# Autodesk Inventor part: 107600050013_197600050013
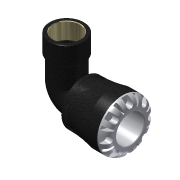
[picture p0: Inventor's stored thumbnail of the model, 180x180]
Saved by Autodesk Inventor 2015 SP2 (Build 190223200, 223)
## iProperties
Created: 2016-12
Part Number: 107600050013_197600050013
Material: PVC-Piping
Description: PLASSON 90° ELBOW WITH FEMALE INTEGRAL BRASS 50X1.1/4" SERIES 1
Document SubType Name: Modeling
Designer: KIM
Mass: 664.223 g
Surface Area: 733.008 cm^2
Volume: 474.445 cm^3
Density: 1.4 g/cm^3
Appearance: Black Cast
Author: KIM
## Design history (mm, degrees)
derived "1076.ipt"
feature "Solid1::1076.ipt"
tag "TaggingFeature1"
body "Solid1"
other parameters: "d1" = 33.18, "d3" = 62.5, "d4" = 85, "d8" = 74.8, "d13" = 9, "d14" = 9, "d15" = 0, "d17" = 360 deg, "d19" = 8 deg, "d20" = 1, "d21" = 1, "d22" = 8 deg, "d24" = 0, "d26" = 360 deg, "d33" = 8.5, "d51" = 0.85, "d54" = 17.5, "d55" = 11, "d57" = 17.64, "d58" = 0, "d74" = 0, "d78" = 79, "d82" = 1, "d115" = 360 deg, "d207" = 90 deg, "d228" = 14.875, "d248" = 4.74, "d270" = 122, "d279" = 67, "d281" = 5.8428, "d294" = 38.952, "d295" = 21, "d296" = 23.1, "d297" = 35.0568, "d299" = 45.57384, "d300" = 35.0568, "d301" = 0, "d302" = 0, "d306" = 2.53188, "d309" = 79.79, "d310" = 14.61308, "d312" = 15 deg, "d313" = 0.68, "d314" = 9.006, "d315" = 0.425, "E_" = 85, "l_" = 79, "A_" = 122, "A_1" = 67, "l_2" = 21, "Rp_" = 38.952, "d9" = 11.25, "d11" = 85, "d12" = 62.5, "d298" = 50.6376
